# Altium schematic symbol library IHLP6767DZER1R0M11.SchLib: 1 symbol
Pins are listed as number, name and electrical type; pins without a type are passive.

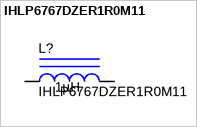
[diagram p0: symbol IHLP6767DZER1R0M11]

## IHLP6767DZER1R0M11
designator L?  ValueDisplayed: 1µH
INDUCTOR POWER 1.0UH 41A SMD; Manufacturer: Vishay-Dale; Alternate Manufacturer: Any; Alternate PartNumber: Equivalent; Value: 1uH; Ind_H: 1.0E-6; Imax_A: 41; Irms: 32A @ 40C rise; Isat: 49A @ 20% inductance drop; Value1: 0.0018 ohm; Material: Powdered Iron; Expr1028: Digi-Key; U/M: EA
signal-integrity model Inductor
simulation model Inductor
footprint IHLP6767DZ (IHLP6767DZ VISHAY DALE INDUCTOR)
pins: 1, 2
